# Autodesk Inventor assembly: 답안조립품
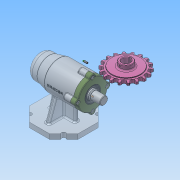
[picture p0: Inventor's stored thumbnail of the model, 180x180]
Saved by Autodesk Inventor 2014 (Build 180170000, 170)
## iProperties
Created: 2021-01
Part Number: 답안조립품
Document SubType Name: Assembly
Designer: NET
Author: NET
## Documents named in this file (12)
- C:\Users\NET\Desktop\710106V1008\답안조립품.iam
- C:\Users\NET\Desktop\710106V1008\본체.ipt
- C:\Users\NET\Desktop\710106V1008\베어링 6004.ipt
- C:\Users\NET\Desktop\710106V1008\베어링 51202.ipt
- C:\Users\NET\Desktop\710106V1008\볼트 M4.ipt
- C:\Users\NET\Desktop\710106V1008\어댑터슬리브.ipt
- C:\Users\NET\Desktop\710106V1008\축.ipt
- C:\Users\NET\Desktop\710106V1008\오일 실.ipt
- C:\Users\NET\Desktop\710106V1008\커버.ipt
- C:\Users\NET\Desktop\710106V1008\키 5 x 5 x 14.ipt
- C:\Users\NET\Desktop\710106V1008\멈춤나사 M3.ipt
- C:\Users\NET\Desktop\710106V1008\스프로킷.ipt
